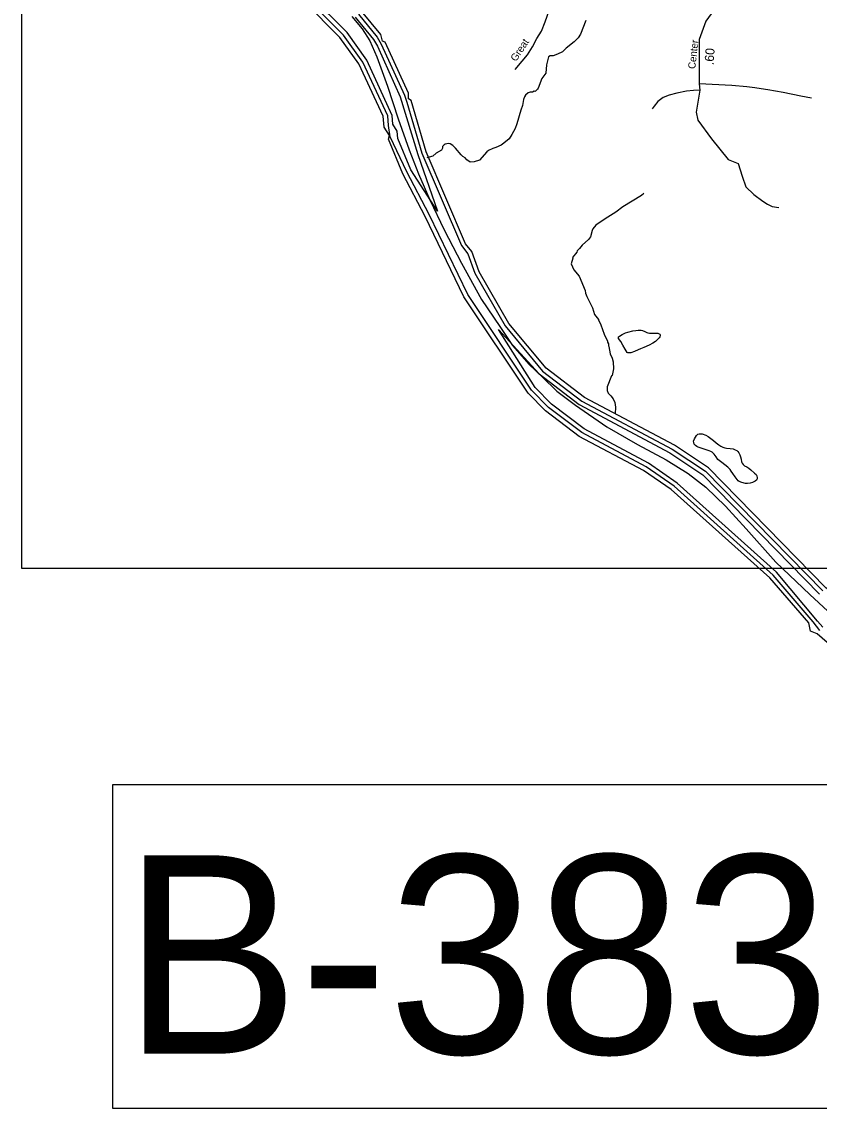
# Model space of a CAD drawing. Extents: x 1551653 to 1702041, y 811336 to 920032.
# Drawn here: x 1569097 to 1576282, y 826375 to 836233 of the extents above; entities that cross this region are included whole.
import ezdxf

# ---------------------------------------------------------------- set-up
doc = ezdxf.new("R2010")
doc.units = 0
for name, color, linetype in [('Old_Level_10', 7, 'Continuous'), ('Old_Level_11', 7, 'Continuous'), ('Old_Level_17', 7, 'Continuous'), ('Old_Level_3', 7, 'Continuous'), ('Old_Level_32', 7, 'Continuous'), ('Old_Level_35', 7, 'Continuous'), ('Old_Level_52', 7, 'Continuous'), ('Old_Level_60', 7, 'Continuous'), ('Old_Level_61', 7, 'Continuous'), ('Old_Level_62', 7, 'Continuous'), ('Old_Level_63', 7, 'Continuous')]:
    doc.layers.add(name, color=color, linetype=linetype)

msp = doc.modelspace()

# ---------------------------------------------------------------- linework, layer by layer
at = {"layer": 'Old_Level_3'}
msp.add_lwpolyline([(1576754.121, 826444.537), (1569917.605, 826444.537), (1569917.605, 829363.138), (1576754.121, 829363.138), (1576754.121, 826444.537)], dxfattribs=at)
at = {"layer": 'Old_Level_32'}
msp.add_lwpolyline([(1575542.323, 837595.436), (1575574.18, 837313.037), (1575572.9, 837146.973), (1575560.612, 836992.026), (1575524.076, 836750.6), (1575474.017, 836572.962), (1575381.211, 836404.213), (1575260.791, 836239.428), (1575201.004, 836074.127), (1575201.105, 835675.898), (1575206.45, 835617.03), (1575173.8, 835420.829), (1575187.453, 835347.952), (1575310.328, 835179.423), (1575460.508, 834992.676), (1575551.526, 834956.237), (1575587.934, 834842.367), (1575619.791, 834746.715), (1575692.605, 834678.393)], dxfattribs=at)
at = {"layer": 'Old_Level_35'}
for points in [[(1573542.254, 835803.23), (1573605.354, 835878.427), (1573652.152, 835935.73), (1573699.255, 836006.928), (1573738.352, 836082.429), (1573779.353, 836149.828), (1573812.653, 836233.426), (1573850.153, 836334.929), (1573881.452, 836428.528), (1573906.754, 836522.228), (1573921.951, 836600.027), (1573927.653, 836711.926), (1573927.151, 836818.028), (1573922.351, 836904.127), (1573913.552, 836984.426), (1573908.352, 837032.526), (1573891.052, 837086.725), (1573846.354, 837185.426)], [(1576213.748, 835546.43), (1576116.048, 835563.828), (1575958.45, 835598.031), (1575820.648, 835622.23), (1575760.75, 835629.028), (1575700.95, 835639.829), (1575631.049, 835646.83), (1575495.048, 835658.828), (1575201.105, 835675.898)], [(1575206.45, 835617.03), (1575150.351, 835613.828), (1575086.152, 835608.73), (1574997.95, 835592.03), (1574931.552, 835573.031), (1574877.251, 835551.63), (1574828.75, 835514.429), (1574796.05, 835472.831), (1574777.75, 835449.028)], [(1575692.605, 834678.393), (1575775.689, 834617.578), (1575816.641, 834592.226), (1575857.594, 834570.776), (1575918.048, 834561.025)]]:
    msp.add_lwpolyline(points, dxfattribs=at)
at = {"layer": 'Old_Level_52'}
msp.add_lwpolyline([(1572069.484, 836281.624), (1572162.188, 836171.205), (1572232.821, 836060.784), (1572294.624, 835919.447), (1572391.743, 835654.439), (1572486.655, 835358.514), (1572588.188, 835080.255), (1572672.064, 834863.832), (1572773.598, 834629.741), (1572903.826, 834360.316), (1573058.334, 834059.973), (1573239.329, 833733.13), (1573402.666, 833490.206), (1573519.65, 833317.95), (1573665.328, 833150.112), (1573788.935, 833030.858), (1573916.956, 832907.188), (1574084.707, 832779.1), (1574367.236, 832584.761), (1574645.349, 832425.756), (1574903.599, 832288.835), (1575102.251, 832165.164), (1575261.174, 832041.494), (1575437.754, 831869.239), (1575623.163, 831666.066), (1575892.448, 831365.723), (1576197.05, 831074.214), (1576439.848, 830848.958)], dxfattribs=at)
at = {"layer": 'Old_Level_60'}
for points in [[(1576500.497, 831022.525), (1576343.53, 831134.021), (1575283.513, 832215.825), (1574978.498, 832418.98), (1574167.517, 832849.026), (1573820.467, 833112.108), (1573485.514, 833516.112), (1573216.486, 833981.119), (1573152.51, 834162.948), (1573095.505, 834233.076), (1572740.457, 835060.923), (1572605.533, 835523.264), (1572580.517, 835540.181), (1572581.439, 835589.393), (1572371.466, 836049.94), (1572346.45, 836060.347), (1572330.456, 836119.709), (1572158.52, 836330.041), (1571821.516, 836658.535), (1571434.481, 836958.526), (1570908.522, 837497.762), (1570744.48, 837724.242)], [(1576204.505, 830742.987), (1576188.511, 830818.806), (1575836.539, 831223.117), (1574947.535, 832019.129), (1574699.525, 832191.578), (1574120.458, 832498.695), (1573815.443, 832728.148), (1573659.501, 832888.857), (1573080.536, 833757.355), (1572731.435, 834480.061), (1572529.459, 834864.944), (1572400.481, 835176.162), (1572409.503, 835208.816), (1572360.496, 835285.301), (1572353.524, 835383.931), (1572134.528, 835854.525), (1571963.515, 836091.002), (1571642.506, 836412.626), (1571132.439, 836843.236), (1570959.478, 837020.657), (1570893.451, 837048.288)], [(1580668.489, 826375.173), (1580662.542, 826559.104), (1580637.526, 826592.477), (1580565.552, 827335.791), (1580330.563, 827832.94), (1580035.493, 828186.91), (1579780.511, 828408.726), (1579524.503, 828578.047), (1579146.49, 828923.868), (1578832.555, 829169.777), (1577169.48, 830027.458), (1576789.518, 830274.751), (1576740.511, 830344.725), (1576649.468, 830385.941), (1576262.534, 830718.791), (1576204.505, 830742.987)]]:
    msp.add_lwpolyline(points, dxfattribs=at)
at = {"layer": 'Old_Level_61'}
for points in [[(1576288.576, 830749.139), (1576227.676, 830827.058), (1575866.681, 831249.363), (1574974.192, 832048.913), (1574722.388, 832224.438), (1574141.988, 832532.579), (1573841.997, 832758.239), (1573690.771, 832914.079), (1573115.395, 833777.245), (1572767.422, 834497.44), (1572565.753, 834881.913), (1572416.27, 835197.949), (1572399.661, 835298.271), (1572393.407, 835386.751), (1572170.823, 835871.391), (1571995.913, 836114.429), (1571670.803, 836440.872)], [(1572099.465, 836275.908), (1572264.634, 836073.829), (1572300.416, 836012.98), (1572507.313, 835559.045), (1572663.665, 835038.521), (1572843.086, 834528.813), (1572601.945, 834898.932), (1572484.962, 835181.391), (1572478.811, 835248.802), (1572438.826, 835311.292), (1572433.289, 835389.57), (1572207.014, 835888.257), (1572028.311, 836137.857), (1571699.1, 836469.118)], [(1572128.992, 836302.974), (1572297.545, 836096.795), (1572335.89, 836031.435), (1572544.428, 835574.219), (1572567.496, 835510.807), (1572702.01, 835049.696), (1573058.698, 834217.287), (1573117.036, 834143.11), (1573178.756, 833967.841), (1573450.86, 833496.068), (1573789.709, 833086.579), (1574143.321, 832817.141), (1574957.993, 832384.583), (1575257.882, 832184.863), (1576314.925, 831106.032)], [(1576314.72, 830779.436), (1576266.738, 830835.312), (1575896.927, 831275.662), (1575000.952, 832078.748), (1574745.149, 832257.246), (1574163.519, 832566.413), (1573868.551, 832788.331), (1573722.042, 832939.3), (1573392.831, 833461.209), (1573758.849, 833061.05), (1574119.228, 832785.255), (1574937.488, 832350.185), (1575232.25, 832153.848), (1576286.423, 831078.042)]]:
    msp.add_lwpolyline(points, dxfattribs=at)
at = {"layer": 'Old_Level_62'}
for points in [[(1574180.128, 836244.484), (1574132.146, 836121.863), (1574109.795, 836090.13), (1574073.398, 836052.606), (1574000.707, 835995.55), (1573967.899, 835963.46), (1573924.736, 835941.314), (1573884.238, 835926.704), (1573859.016, 835927.011), (1573841.792, 835917.579), (1573824.978, 835845.811), (1573818.109, 835769.941), (1573781.507, 835722.421), (1573750.544, 835636.863), (1573744.392, 835626.969), (1573722.144, 835607.233), (1573714.147, 835607.335), (1573698.051, 835599.543), (1573678.058, 835599.8), (1573660.013, 835594.007), (1573635.715, 835572.323), (1573625.565, 835556.482), (1573617.26, 835532.594), (1573608.648, 835480.716), (1573592.141, 835436.937), (1573558.718, 835313.445), (1573542.211, 835273.665), (1573513.606, 835218.044), (1573487.155, 835178.366), (1573440.71, 835138.996), (1573416.514, 835123.31), (1573368.224, 835099.883), (1573340.542, 835093.782), (1573302.505, 835074.097), (1573287.229, 835061.692), (1573220.792, 834986.899), (1573172.707, 834972.391), (1573137.438, 834970.29), (1573107.398, 834990.846), (1573091.609, 835008.173), (1573071.309, 835019.656), (1573055.52, 835033.856), (1573004.257, 835096.5), (1572980.573, 835118.748), (1572956.685, 835133.05), (1572940.793, 835137.253), (1572912.701, 835131.614), (1572902.654, 835125.77), (1572888.402, 835109.931), (1572888.3, 835093.936), (1572878.047, 835076.097), (1572831.706, 835050.67), (1572799.41, 835023.091), (1572747.634, 835009.608)], [(1574701.063, 834687.369), (1574680.865, 834669.581), (1574513.645, 834565.773), (1574449.874, 834519.688), (1574352.372, 834459.813), (1574269.736, 834400.911), (1574243.387, 834369.231), (1574235.185, 834353.339), (1574222.574, 834297.514), (1574204.222, 834273.779), (1574147.627, 834222.516), (1574123.329, 834190.835), (1574100.978, 834169.1), (1574096.877, 834159.155), (1574060.378, 834111.634), (1574061.505, 834105.483), (1574047.664, 834051.862), (1574071.04, 833999.573), (1574118.305, 833942.979), (1574172.849, 833814.36), (1574176.54, 833790.318), (1574188.125, 833758.227), (1574238.978, 833657.597), (1574258.253, 833597.415), (1574293.727, 833552.97), (1574292.497, 833547.536), (1574313.104, 833504.731), (1574344.067, 833420.404), (1574375.338, 833356.018), (1574375.235, 833348.02), (1574383.027, 833331.924), (1574382.822, 833315.981), (1574386.718, 833307.933), (1574397.996, 833243.802), (1574417.476, 833203.561), (1574425.165, 833171.471), (1574428.344, 833107.494), (1574415.63, 833047.67), (1574409.581, 833043.056), (1574370.416, 832944.273), (1574370.109, 832912.285), (1574379.746, 832888.191), (1574403.532, 832863.893), (1574425.165, 832835.646), (1574440.749, 832803.453), (1574446.286, 832763.417), (1574443.517, 832701.235)], [(1574506.673, 833415.226), (1574535.893, 833431.015), (1574556.501, 833436.961), (1574602.535, 833449.265), (1574629.5, 833454.083), (1574649.492, 833455.263), (1574676.354, 833455.314), (1574690.503, 833452.955), (1574709.88, 833444.19), (1574728.642, 833434.347), (1574738.587, 833431.579), (1574753.864, 833428.657), (1574775.394, 833427.221), (1574792.209, 833427.939), (1574808.613, 833428.708), (1574827.477, 833427.324), (1574835.372, 833424.556), (1574844.702, 833419.122), (1574847.778, 833414.867), (1574848.188, 833406.921), (1574846.445, 833396.464), (1574841.011, 833385.493), (1574826.042, 833370.525), (1574807.28, 833353.967), (1574783.904, 833338.075), (1574749.353, 833319.774), (1574700.55, 833299.064), (1574671.33, 833287.478), (1574651.748, 833277.841), (1574616.684, 833262.667), (1574585.413, 833250.621), (1574570.137, 833250.364), (1574559.167, 833251.082), (1574552.4, 833255.439), (1574533.843, 833283.121), (1574512.415, 833319.313), (1574493.448, 833352.275), (1574474.993, 833381.034), (1574473.045, 833390.569), (1574474.788, 833395.798), (1574483.81, 833403.025), (1574506.673, 833415.226)], [(1575541.981, 832109.044), (1575524.142, 832133.497), (1575503.124, 832165.895), (1575490.411, 832186.4), (1575478.928, 832200.959), (1575457.705, 832221.567), (1575430.638, 832243.61), (1575403.571, 832264.371), (1575381.016, 832280.468), (1575369.43, 832291.746), (1575354.769, 832313.584), (1575334.264, 832338.087), (1575316.322, 832355.414), (1575306.582, 832361.463), (1575291.1, 832368.948), (1575263.111, 832378.585), (1575218.922, 832391.811), (1575192.983, 832400.731), (1575179.347, 832407.549), (1575166.429, 832416.93), (1575156.894, 832428.157), (1575151.255, 832442.664), (1575150.845, 832456.351), (1575156.996, 832475.831), (1575176.476, 832508.178), (1575187.139, 832518.431), (1575199.647, 832522.788), (1575214.001, 832523.147), (1575228.969, 832520.276), (1575260.137, 832508.588), (1575280.848, 832497.105), (1575306.069, 832481.009), (1575329.24, 832460.965), (1575354.359, 832440.306), (1575376.915, 832422.876), (1575396.292, 832410.778), (1575415.054, 832402.628), (1575431.971, 832396.425), (1575448.273, 832393.503), (1575479.543, 832390.325), (1575506.2, 832385.301), (1575524.45, 832379.098), (1575538.701, 832371.665), (1575548.953, 832363.616), (1575557.258, 832351.723), (1575566.075, 832333.935), (1575572.944, 832313.533), (1575577.866, 832293.233), (1575582.684, 832270.267), (1575586.99, 832257.143), (1575595.91, 832244.533), (1575609.444, 832233.87), (1575629.539, 832223.72), (1575649.634, 832213.518), (1575665.73, 832198.909), (1575700.384, 832166.92), (1575713.302, 832155.591), (1575718.941, 832144.365), (1575723.863, 832125.346), (1575723.042, 832114.888), (1575718.326, 832103.867), (1575705.716, 832095.613), (1575682.032, 832083.618), (1575659.681, 832076.185), (1575634.768, 832073.365), (1575617.851, 832074.339), (1575585.35, 832082.797), (1575560.641, 832092.384), (1575551.004, 832099.048), (1575541.981, 832109.044)]]:
    msp.add_lwpolyline(points, dxfattribs=at)
at = {"layer": 'Old_Level_63'}
msp.add_lwpolyline([(1569096.749, 874749.337), (1631612.821, 874749.337), (1631612.821, 831307.151), (1569096.749, 831307.151), (1569096.749, 874749.337)], dxfattribs=at)

# ---------------------------------------------------------------- texts
at = {"layer": 'Old_Level_10'}
msp.add_text('Great', height=65.6167, rotation=56.5120806, dxfattribs=at).set_placement((1573549.296, 835870.503))
at = {"layer": 'Old_Level_11'}
msp.add_text('Center', height=65.6167, rotation=83.6601417, dxfattribs=at).set_placement((1575164.971, 835806.013))
at = {"layer": 'Old_Level_17'}
msp.add_text('.60', height=82.0208, rotation=85.5952444, dxfattribs=at).set_placement((1575329.234, 835841.679))
at = {"layer": 'Old_Level_3'}
msp.add_text('B-3835', height=1788.0542, dxfattribs=at).set_placement((1570003.524, 826937.36))

doc.saveas('drawing.dxf')
